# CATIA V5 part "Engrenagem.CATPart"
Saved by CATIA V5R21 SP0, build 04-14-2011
Part number: Engrenagem
Bounding box of the stored display mesh (mm): x 0 to 3, y -12.98 to 12.993, z -12.835 to 13
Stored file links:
  D:\CATIA\CADs\CHASSI\Direita\Motor\Engrenagem.CATPart
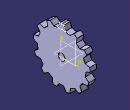
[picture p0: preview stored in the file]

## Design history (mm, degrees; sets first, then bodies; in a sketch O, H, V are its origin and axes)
Body1 (main body)
  Sketch1 on yz-plane, origin (0, 0, 0), H (0, 1, 0), V (0, 0, 1)
    circle A1 centre (0, 0) radius 11
    circle A2 centre (0, 0) radius 1.6
    point P1 (0, 1.6)
    radius A1 = 11
    radius A2 = 1.6
    coincidence: A2 P1, P1 V
  Pad1: profile Sketch1, direction (1, 0, 0), length 3
  Sketch2 on end face of Pad1, origin (3, 0, 0), H (0, 1, 0), V (0, 0, 1)
    arc A1 centre (0, 0) radius 11 from (1.6163, 10.8806) to (0, 11) ccw
    arc A2 centre (0, 0) radius 13 from (0.9198, 12.9674) to (0, 13) ccw
    point P1 (0, 13)
    point P2 (1.6163, 10.8806)
    line L1 (0.9198, 12.9674) -> (1.6163, 10.8806)
    point P3 (0.9198, 12.9674)
    point P4 (0, 0)
    point P5 (0, 11)
    axis line L2 (0, 13) -> (0, 0)
    point P6 (0, 13)
    point P7 (0, 13)
    point P8 (-0.9198, 12.9674)
    arc A3 centre (0, 0) radius 13 from (-0.9198, 12.9674) to (0, 13) cw
    point P10 (-1.6163, 10.8806)
    line L3 (-0.9198, 12.9674) -> (-1.6163, 10.8806)
    point P11 (0, 11)
    arc A4 centre (0, 0) radius 11 from (-1.6163, 10.8806) to (0, 11) cw
    radius A1 = 11
    radius A2 = 13
    length L1 = 2.2
    distance P3 P8 = 1.8395
    coincidence: P1 V, P4 V, P6 A2
    vertical: L2 V
    symmetry: P1 P7 L2, P3 P8 L2, A2 A3 L2, P2 P10 L2, L1 L3 L2, P5 P11 L2, A1 A4 L2
  Pad2: profile Sketch2, direction (1, 0, 0), length -3
  CircPattern1: of the body so far, instances 13, angular step 27.6, axis from face of Pad1 from Sketch1.A1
